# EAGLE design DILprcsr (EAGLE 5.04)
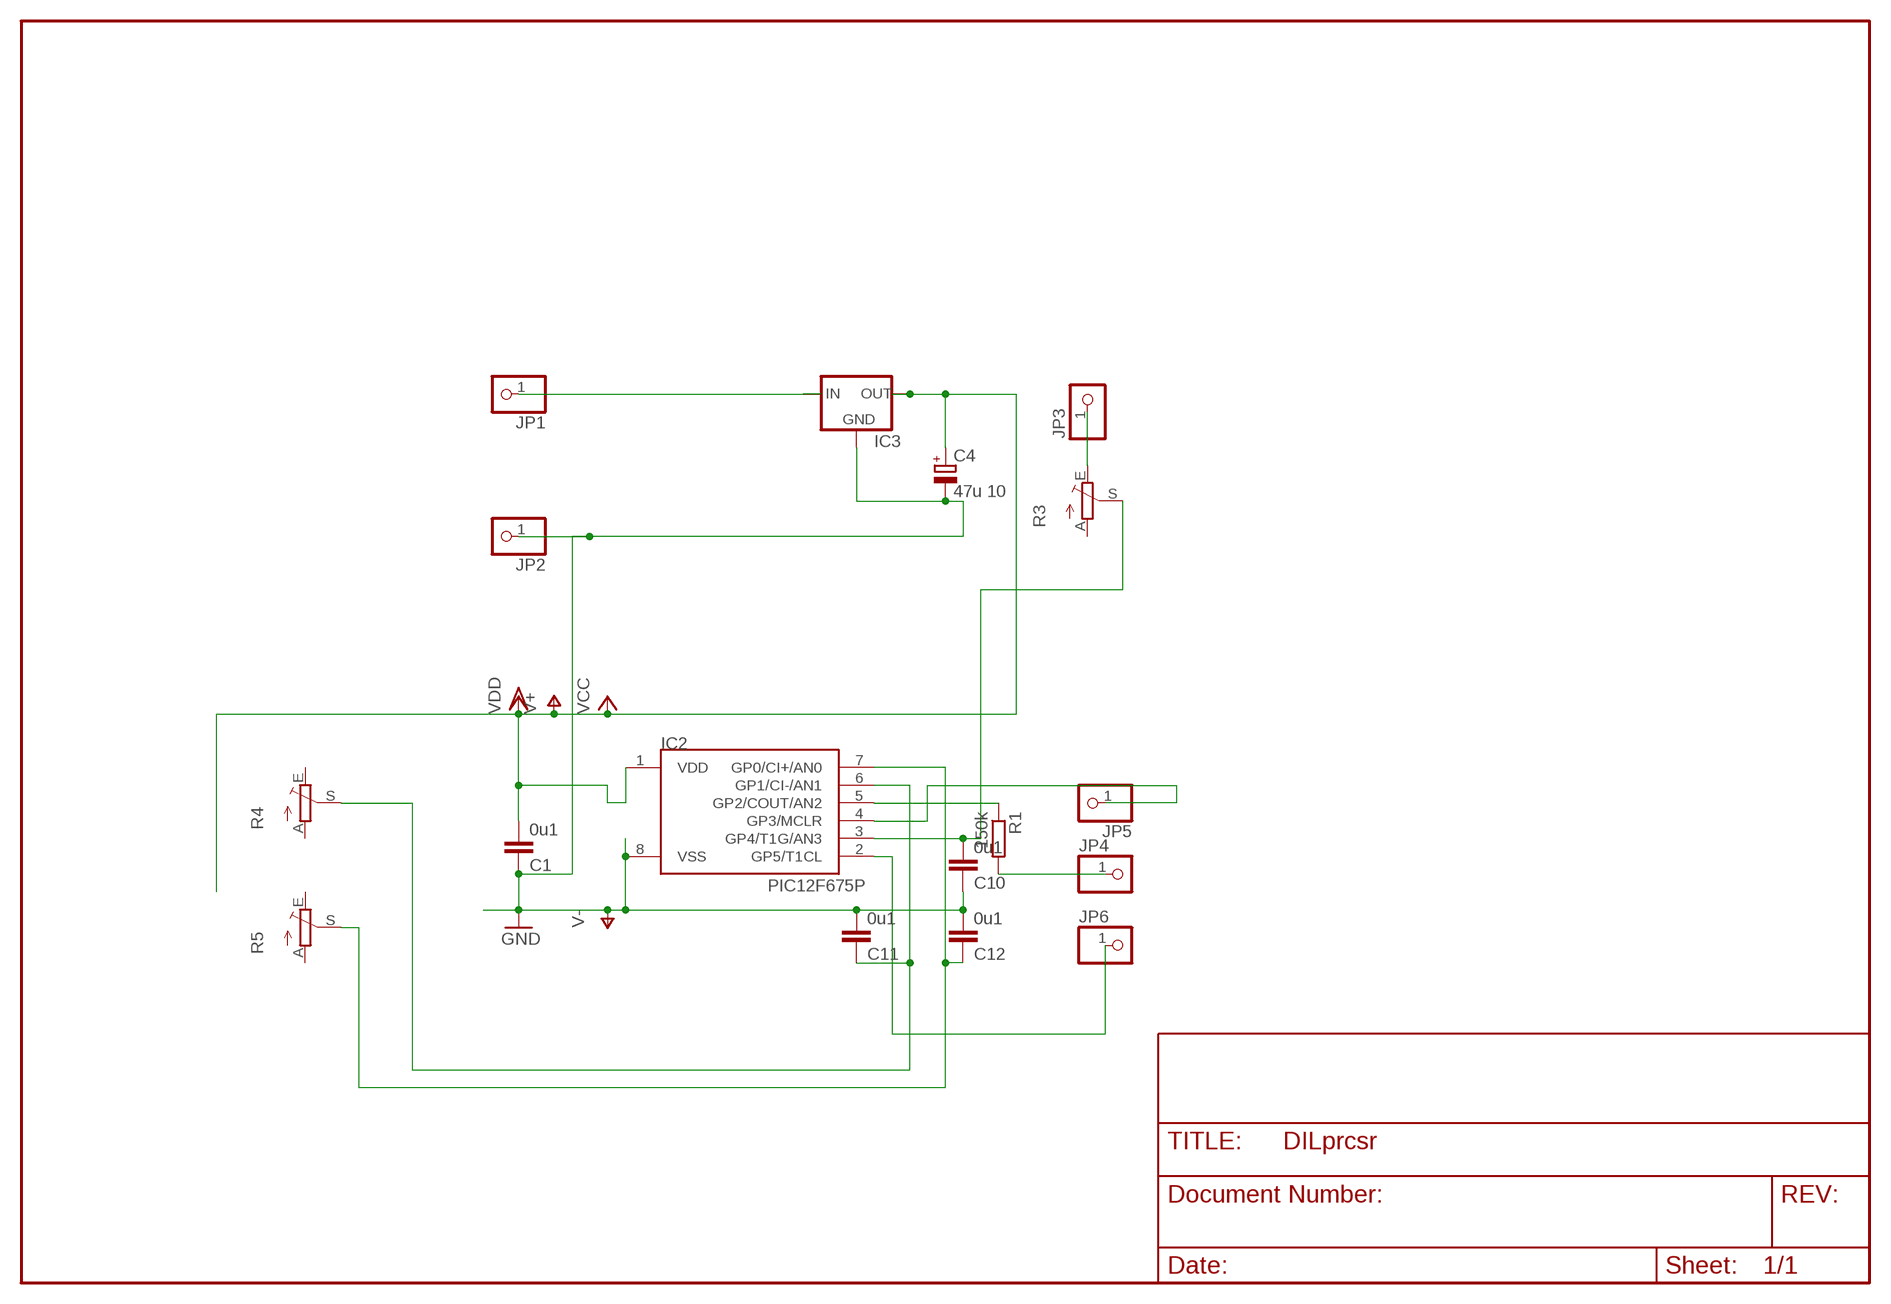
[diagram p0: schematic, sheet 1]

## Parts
C1  0u1  C-EUC1206  [C1206]
C4  47u 10  CPOL-EUE2.5-6  [E2,5-6]
C10  0u1  C-EUC1206  [C1206]
C11  0u1  C-EUC1206  [C1206]
C12  0u1  C-EUC1206  [C1206]
IC2  PIC12F675P  [DIL8]
IC3  78LXX  [78LXX]
JP1  PINHD-1X1  [1X01]
JP2  PINHD-1X1  [1X01]
JP3  PINHD-1X1  [1X01]
JP4  PINHD-1X1  [1X01]
JP5  PINHD-1X1  [1X01]
JP6  PINHD-1X1  [1X01]
R1  150k  R-EU_0204/2V  [0204V]
R3  TRIM_EU-CA6V  [CA6V]
R4  TRIM_EU-CA6V  [CA6V]
R5  TRIM_EU-CA6V  [CA6V]

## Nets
N$1: JP3.1 R3.E
N$2: JP4.1 R1.2
N$3: IC2.4(GP3/MCLR) JP5.1
N$4: IC2.2(GP5/T1CL) JP6.1
N$5: IC2.5(GP2/COUT/AN2) R1.1
N$12: C10.2 IC2.3(GP4/T1G/AN3) R3.S
N$13: C12.1 IC2.7(GP0/CI+/AN0) R5.S
N$15: C11.1 IC2.6(GP1/CI-/AN1) R4.S
N$20: IC3.IN JP1.1
V+: C1.2 C4.+ IC2.1(VDD) IC3.OUT ; supply symbol labelled VCC, VDD
V-: C1.1 C4.- C10.1 C11.2 C12.2 IC2.8(VSS) IC3.GND JP2.1 ; supply symbol labelled GND
Unconnected: R3.A R4.A R4.E R5.A R5.E

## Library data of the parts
C1 C10-C12 = rcl:C-EU: CAPACITOR, European symbol
C4 = rcl:CPOL-EU: POLARIZED CAPACITOR, European symbol
IC2 = microchip-3:PIC12F6*: uPC nW 1k Program Flash memory 2x Timer Comparator 10b A/D converter/ 4xIN
IC3 = v-reg:78LXX: VOLTAGE REGULATOR
JP1-JP6 = pinhead:PINHD-1X1: PIN HEADER
R1 = rcl:R-EU_: RESISTOR, European symbol
R3-R5 = pot:TRIM_EU-: POTENTIOMETER

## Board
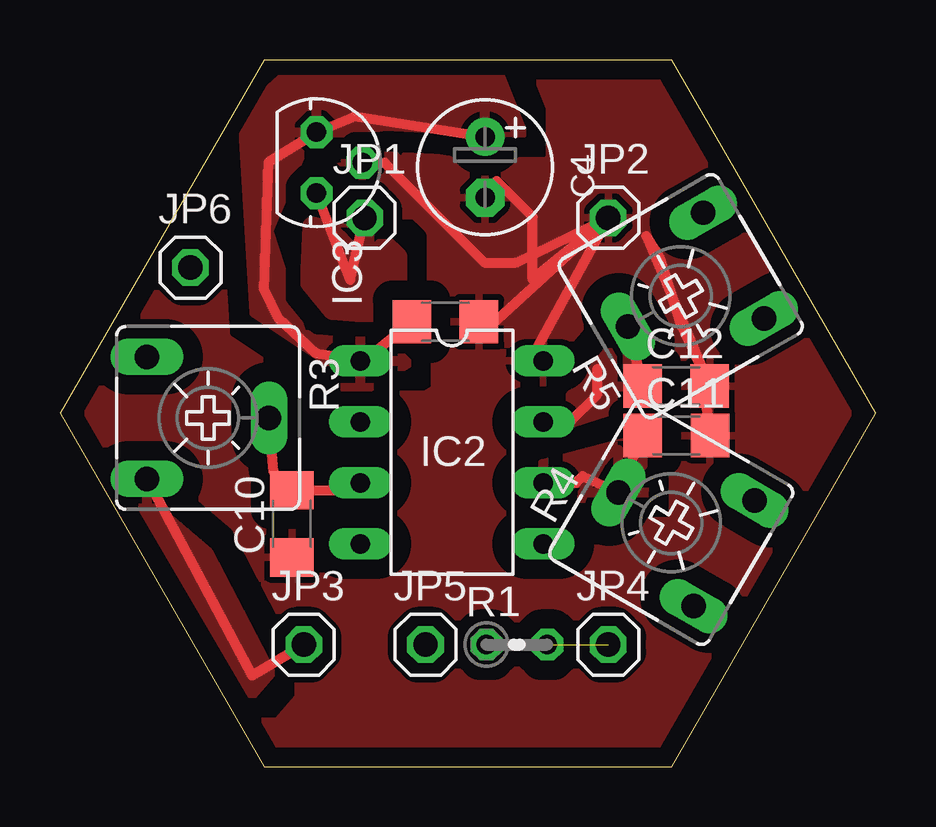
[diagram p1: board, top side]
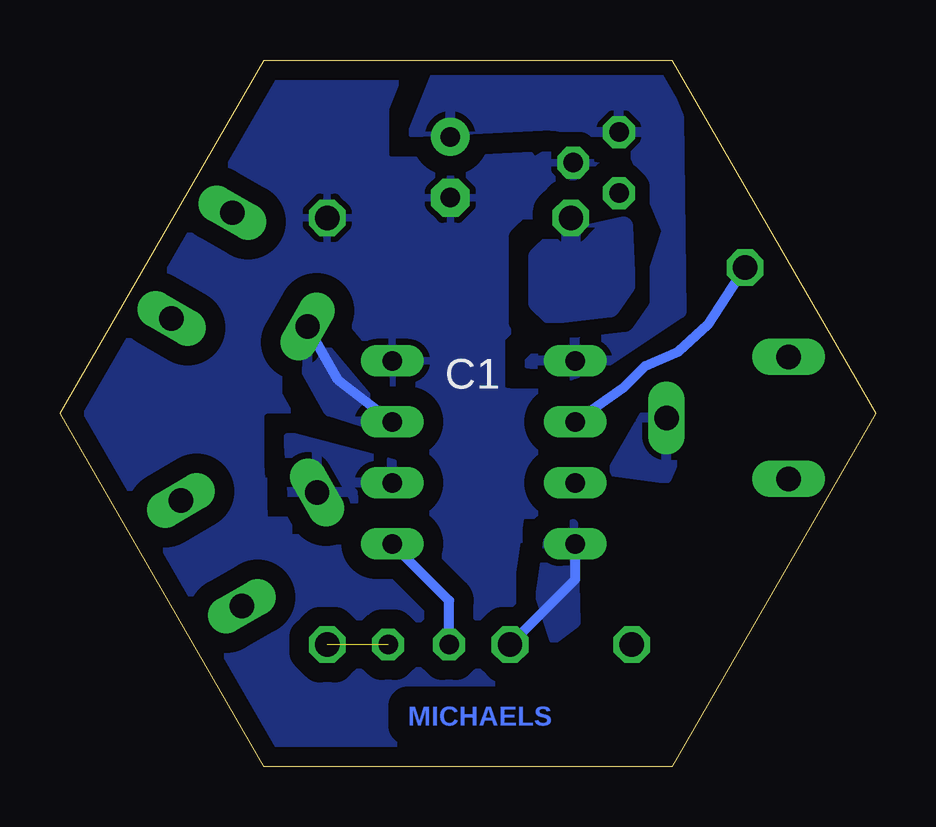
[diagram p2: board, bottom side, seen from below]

Size 34 x 29.44 mm. Coordinates in mm from the lower left corner, seen from the top.
Outline: 8.5,0 25.5,0 34,14.72 25.5,29.44 8.5,29.44 0,14.72 8.5,0
Copper layers (1*16): Top 0.035mm / dielectric 1.5mm / Bottom 0.035mm
Design rules "default *": minimum track width 10mil, minimum drill 24mil, track to track 8mil, track to pad 8mil, pad to pad 8mil, via to via 8mil, smd to smd 8mil, copper to edge 10mil, drill to drill 8mil, minimum pad ring 10mil, minimum via ring 8mil, stop-mask expansion 4mil, vias tented up to drill 0mil, thermal gap 10mil

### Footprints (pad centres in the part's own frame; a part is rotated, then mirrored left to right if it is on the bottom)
C1206 = smd 1.6 x 1.8: 1 -1.4,0; 2 1.4,0
E2,5-6 = drill 0.813 pad 1.6 round: + -1.27,0 | drill 0.813 pad 1.6 octagon: - 1.27,0
DIL8 = drill 0.813 long: 1 -3.81,-3.81; 2 -1.27,-3.81; 3 1.27,-3.81; 4 3.81,-3.81; 5 3.81,3.81; 6 1.27,3.81; 7 -1.27,3.81; 8 -3.81,3.81
78LXX = drill 0.813 octagon: GND 0,1.905; IN 1.27,0; OUT -1.27,0
1X01 = drill 1.016 octagon: 1 0,0
0204V = drill 0.813 octagon: 1 -1.27,0; 2 1.27,0
CA6V = drill 1.016 long: A -2.54,-2.54; E 2.54,-2.54; S 0,2.54

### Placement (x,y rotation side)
C1  16.06,18.54 180 top
C4  17.72,24.97 270 top
C10  9.67,10.11 90 top
C11  25.7,13.79 0 top
C12  25.68,15.85 0 top
IC2  16.34,13.09 270 top
IC3  10.7,25.16 270 top
JP1  12.7,22.86 0 top
JP2  22.86,22.86 0 top
JP3  10.16,5.08 0 top
JP4  22.86,5.08 0 top
JP5  15.24,5.08 0 top
JP6  5.44,20.79 0 top
R1  19.05,5.08 0 top
R3  6.17,14.53 270 top
R4  25.48,10.15 60 top
R5  25.88,19.6 120 top

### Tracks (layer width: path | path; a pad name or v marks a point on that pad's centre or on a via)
N$1
  Top 0.406: JP3.1 8,3.8 R3.E
  pour Top (isolate 0.61): 2.9,11.7 8,3 8.8,3.9 6.2,8.9
  pour Bottom (isolate 0.61): 4.1,12 9.2,3.3 8.9,6.1 7,8.3
N$2  (1 unrouted)
N$3
  Bottom 0.406: IC2.4 12.53,7.79 JP5.1
  pour Bottom (isolate 0.61): 12.6,10.1 13.6,9.8 14,7.1 13.4,5.3 12.5,6
N$4
  Bottom 0.406: IC2.2 10.5,15.8 9.6,16.7 8.2,17.3 7,18.4 JP6.1
N$5
  Bottom 0.406: R1.1 17.78,6.91 IC2.5
N$12
  Top 0.406: R3.S 8.91,12.27 C10.2 12.22,11.51 IC2.3
  pour Bottom (isolate 0.61): 9.5,14.9 11,12.3 8.7,12 7.9,13.8
N$13
  Top 0.406: R5.S C12.1 | IC2.7 21.26,14.36 22.4,15.5 22.4,16.56
  Bottom 0.406: R5.S 22.4,16.1 IC2.7
  pour Top (isolate 0.61): 20.9,14.2 22.8,14.8 24.3,17.5 23.5,18.1 20.3,14.3
  pour Bottom (isolate 0.406): 20.9,14.2 22.8,14.8 24.3,17.5 23.5,18.1 20.3,14.3
N$15
  Top 0.406: C11.1 R4.S 21.8,12.1 21.52,11.82 IC2.6
  pour Top (isolate 0.61, rank 2): 20.1,12.6 24.3,13.7 24.5,13.7 24.3,11.1 23.6,10.7 20.7,11.4
  pour Bottom (isolate 0.61, rank 2): 20.1,12.6 24.3,13.7 24.5,13.7 24.3,11.1 23.6,10.7 20.7,11.4
N$20
  Top 0.406: IC3.IN 12.1,20.28 JP1.1
  pour Top (isolate 0.813): 10.51,22.51 10.41,20.18 11.36,19.02 13.56,18.82 14.06,19.33 14.06,21.24 13.43,21.87
  pour Bottom (isolate 0.813): 10.51,22.51 10.41,20.08 11.06,19.12 13.56,18.82 14.06,19.33 14.06,21.24 13.43,21.87
V+
  Top 0.406: C4.+ 12.3,27.1 IC3.OUT 8.7,25.2 8.5,19.9 9.1,18.7 10.7,17.2 IC2.1 12.59,16.84 C1.2
  pour Top (isolate 0.61, rank 2): 18.3,28.9 9.6,29 7.6,27.2 8.1,18.9 11.4,16.7 12.1,15.3 14.5,16.8 13.6,17.7 10.1,18 8.7,22.3 10.3,26.1 13.5,26.7 19.3,26.4
  pour Bottom (isolate 0.61, rank 2): 18.3,28.9 8.9,28.8 8.2,27.1 8.1,18.9 11.4,16.7 12.7,16.3 14.5,16.8 13.6,17.7 10.1,18 8.7,22.3 10.3,26.1 13.5,26.7 19.3,26.4
V-
  Top 0.406: IC3.GND 13.54,25.16 17.7,21 19,21 JP2.1 | C4.- 18.2,24.4 19.7,22.9 19.7,20.3 JP2.1 | C11.2 26.8,16.5 25.9,18.4 25,21.2 24.44,22.1 C12.2 | JP2.1 19.78,17.27 IC2.8 | C1.1 17.76,18.2 JP2.1
  pour Top (isolate 0.813, rank 4): 14.24,25.25 17.43,29.55 26.6,29.18 28.38,24.21 33.66,14.78 25.09,0.25 9.24,0.25 0.42,14.47 5.82,25.54 8.51,30.44
  pour Bottom (isolate 0.813, rank 4): 14.24,25.25 17.43,29.55 26.6,29.18 28.38,24.21 33.16,14.78 24.79,0.45 9.34,0.45 0.32,14.67 6.02,23.74 8.71,28.64

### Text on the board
Bottom: MICHAELS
